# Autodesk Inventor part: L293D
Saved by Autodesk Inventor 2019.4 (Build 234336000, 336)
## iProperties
Created: 2020-04
Part Number: L293D
Material: Generic
Document SubType Name: Modeling
Designer: Administrator
Density: 1 g/cm^3
Appearance: Default
Title: DIL16
Author: Administrator
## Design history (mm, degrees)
feature "DIL16"
body "Solid1"
